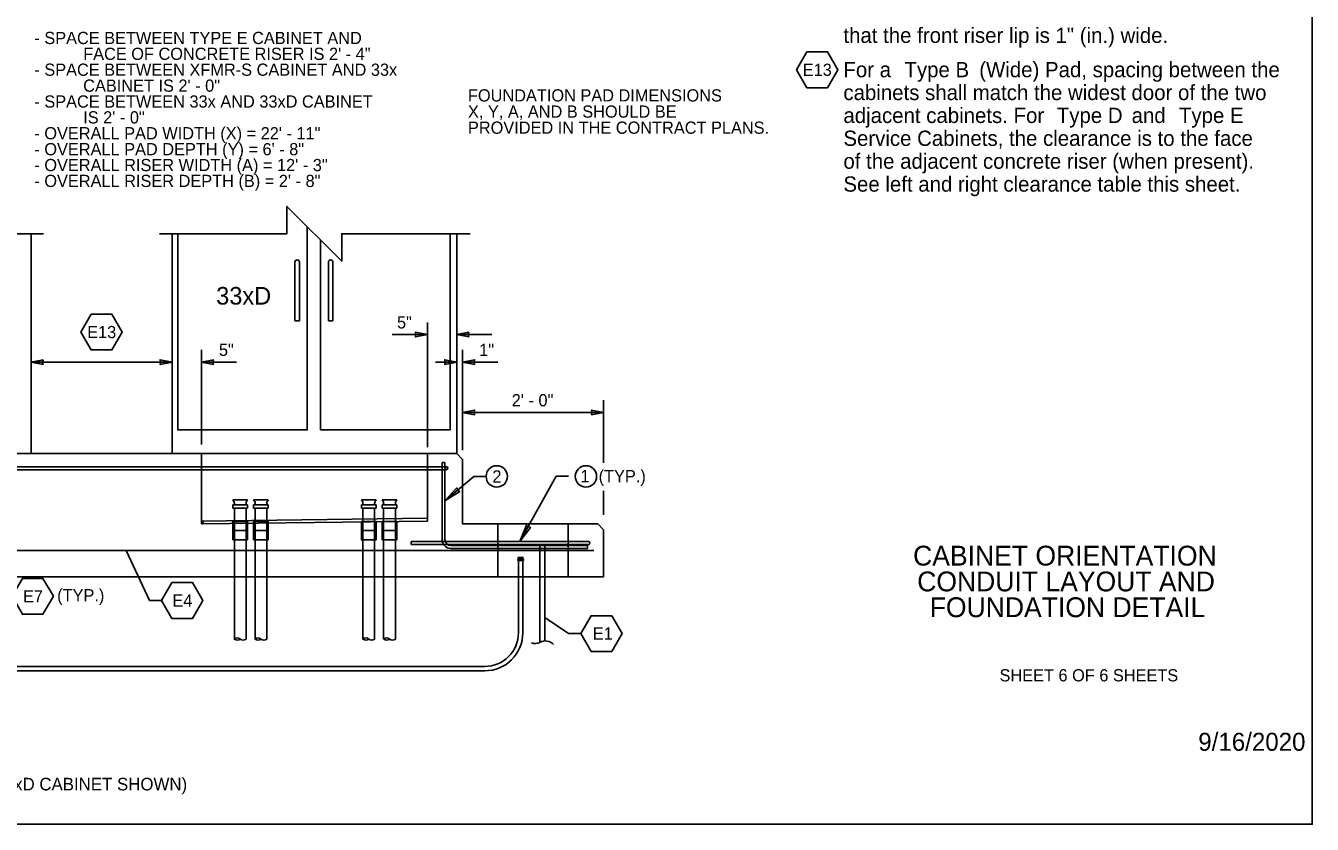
# Model space of a CAD drawing. Extents: x 99862 to 103151, y 100000 to 117076.
# Drawn here: x 101465 to 103151, y 115000 to 116046 of the extents above; entities that cross this region are included whole.
import ezdxf

# ---------------------------------------------------------------- set-up
doc = ezdxf.new("R2010")
doc.units = 0
for name, color, linetype in [('Default', 7, 'Continuous'), ('Level 1', 7, 'Continuous'), ('Level 11', 7, 'Continuous'), ('Level 15', 7, 'Continuous'), ('Level 20', 7, 'Continuous'), ('Level 40', 7, 'Continuous'), ('Level 6', 7, 'Continuous'), ('Level 62', 7, 'Continuous')]:
    doc.layers.add(name, color=color, linetype=linetype)

msp = doc.modelspace()

# ---------------------------------------------------------------- linework, layer by layer
at = {"layer": 'Default'}
for p, q in [((102010.5, 115372.6), (102010.5, 115473.9)), ((102010.5, 115473.9), (102014.3, 115473.9)), ((102014.3, 115372.6), (102014.3, 115473.9)), ((100931.3, 115468.2), (102016.3, 115468.2)), ((100931.3, 115464.3), (102016.3, 115464.3)), ((102202.3, 115370.1), (101969.8, 115370.1)), ((101969.8, 115370.1), (101969.8, 115366.3)), ((101969.8, 115370.1), (101969.8, 115366.3)), ((102202.3, 115366.3), (101969.8, 115366.3)), ((102200.9, 115364.9), (102022, 115364.9)), ((102200.9, 115361.1), (102022, 115361.1)), ((102200.9, 115364.9), (102200.9, 115361.1))]:
    msp.add_line(p, q, dxfattribs=at)
for centre, radius in [((102016.3, 115466.3), 1.92), ((101696.5, 115394.6), 1.44)]:
    msp.add_circle(centre, radius, dxfattribs=at)
for centre, radius, start, end in [((102022, 115372.6), 11.5, 180, 270), ((102022, 115372.6), 7.7, 180, 270), ((102202.3, 115368.2), 1.92, 270, 90)]:
    msp.add_arc(centre, radius, start, end, dxfattribs=at)
at = {"layer": 'Level 1'}
for p, q in [((101656.5, 115773.5), (101656.5, 115485.5)), ((102029.7, 115773.5), (102029.7, 115485.5)), ((101817.7, 115732.5), (101817.7, 115736.4)), ((101817.7, 115659.2), (101817.7, 115732.5)), ((101823.5, 115736.4), (101823.5, 115732.5)), ((101823.5, 115732.5), (101823.5, 115659.2)), ((101861.5, 115736.4), (101861.5, 115732.5)), ((101861.5, 115732.5), (101861.5, 115659.2)), ((101867.3, 115732.5), (101867.3, 115736.4)), ((101867.3, 115659.2), (101867.3, 115732.5)), ((101823.5, 115659.2), (101817.7, 115659.2)), ((101861.5, 115659.2), (101867.3, 115659.2)), ((101736.3, 115424.6), (101755.5, 115424.6)), ((101763.5, 115424.6), (101782.7, 115424.6)), ((101904.8, 115424.6), (101924, 115424.6)), ((101932, 115424.6), (101951.3, 115424.6)), ((101736.3, 115418.3), (101736.3, 115413.7)), ((101736.3, 115418.3), (101755.5, 115418.3)), ((101736.3, 115413.7), (101755.5, 115413.7)), ((101738.2, 115420.1), (101738.2, 115418.3)), ((101738.2, 115384.4), (101738.2, 115413.7)), ((101753.6, 115420.1), (101753.6, 115418.3)), ((101753.6, 115384.4), (101753.6, 115413.7)), ((101755.5, 115418.3), (101755.5, 115413.7)), ((101763.5, 115418.3), (101763.5, 115413.7)), ((101763.5, 115418.3), (101782.7, 115418.3)), ((101763.5, 115413.7), (101782.7, 115413.7)), ((101765.4, 115420.1), (101765.4, 115418.3)), ((101765.4, 115384.4), (101765.4, 115413.7)), ((101780.8, 115420.1), (101780.8, 115418.3)), ((101780.8, 115384.4), (101780.8, 115413.7)), ((101782.7, 115418.3), (101782.7, 115413.7)), ((101904.8, 115418.3), (101904.8, 115413.7)), ((101904.8, 115418.3), (101924, 115418.3)), ((101904.8, 115413.7), (101924, 115413.7)), ((101906.7, 115420.1), (101906.7, 115418.3)), ((101906.7, 115384.4), (101906.7, 115413.7)), ((101922.1, 115420.1), (101922.1, 115418.3)), ((101922.1, 115384.4), (101922.1, 115413.7)), ((101924, 115418.3), (101924, 115413.7)), ((101932, 115418.3), (101932, 115413.7)), ((101932, 115418.3), (101951.3, 115418.3)), ((101932, 115413.7), (101951.3, 115413.7)), ((101933.9, 115420.1), (101933.9, 115418.3)), ((101933.9, 115384.4), (101933.9, 115413.7)), ((101949.3, 115420.1), (101949.3, 115418.3)), ((101949.3, 115384.4), (101949.3, 115413.7)), ((101951.3, 115418.3), (101951.3, 115413.7)), ((101753.6, 115384.4), (101738.2, 115384.4)), ((101738.2, 115384.4), (101738.2, 115242.3)), ((101753.6, 115384.4), (101753.6, 115242.3)), ((101780.8, 115384.4), (101765.4, 115384.4)), ((101765.4, 115384.4), (101765.4, 115242.3)), ((101780.8, 115384.4), (101780.8, 115242.3)), ((101922.1, 115384.4), (101906.7, 115384.4)), ((101906.7, 115384.4), (101906.7, 115242.3)), ((101922.1, 115384.4), (101922.1, 115242.3)), ((101949.3, 115384.4), (101933.9, 115384.4)), ((101933.9, 115384.4), (101933.9, 115242.3)), ((101949.3, 115384.4), (101949.3, 115242.3)), ((102109.8, 115349.3), (102117, 115349.3)), ((102109.8, 115347), (102109.8, 115345.3)), ((102109.8, 115347), (102117, 115347)), ((102109.8, 115345.3), (102117, 115345.3)), ((102110.5, 115347.6), (102110.5, 115347)), ((102110.5, 115249), (102110.5, 115345.3)), ((102116.3, 115347.6), (102116.3, 115347)), ((102116.3, 115248.9), (102116.3, 115345.3)), ((102117, 115347), (102117, 115345.3)), ((100236.1, 115206.3), (102066.3, 115206.3)), ((100236.1, 115200.5), (102066.3, 115200.5))]:
    msp.add_line(p, q, dxfattribs=at)
for points in [[(99862, 114999.5), (103151, 114999.5), (103151, 117075.5), (99862, 117075.5)], [(101755.5, 115372.5), (101736.3, 115372.5), (101736.3, 115396.3), (101755.5, 115396.3)], [(101782.7, 115372.5), (101763.5, 115372.5), (101763.5, 115396.3), (101782.7, 115396.3)], [(101924, 115372.5), (101904.8, 115372.5), (101904.8, 115396.3), (101924, 115396.3)], [(101951.3, 115372.5), (101932, 115372.5), (101932, 115396.3), (101951.3, 115396.3)], [(102138.8, 115366.3), (102138.8, 115237.8), (102141, 115238.9), (102143, 115239.5), (102145.1, 115239.8), (102145.1, 115366.3)]]:
    msp.add_lwpolyline(points, close=True, dxfattribs=at)
for points in [[(101833.8, 115782.8), (101833.8, 115516.4), (101664, 115516.4), (101664, 115773.5)], [(102021, 115773.5), (102021, 115516.4), (101851.2, 115516.4), (101851.2, 115765.4)]]:
    msp.add_lwpolyline(points, dxfattribs=at)
for centre, radius, start, end in [((101820.6, 115736.4), 2.9, 0, 180), ((101864.4, 115736.4), 2.9, 0, 180), ((101731.9, 115420.1), 6.32, 0, 45.9402), ((101759.9, 115420.1), 6.32, 134.0598, 180), ((101759.1, 115420.1), 6.32, 0, 45.9402), ((101787.1, 115420.1), 6.32, 134.0598, 180), ((101900.4, 115420.1), 6.32, 0, 45.9402), ((101928.4, 115420.1), 6.32, 134.0598, 180), ((101927.6, 115420.1), 6.32, 0, 45.9402), ((101955.7, 115420.1), 6.32, 134.0598, 180), ((102108.1, 115347.6), 2.37, 0, 45.9402), ((102118.6, 115347.6), 2.37, 134.0598, 180), ((101742, 115237.6), 6.09, 50.8329, 129.1671), ((101742, 115247), 6.09, 230.8329, 309.1671), ((101749.7, 115247), 6.09, 230.8329, 309.1671), ((101769.2, 115237.6), 6.09, 50.8329, 129.1671), ((101769.2, 115247), 6.09, 230.8329, 309.1671), ((101776.9, 115247), 6.09, 230.8329, 309.1671), ((101910.6, 115237.6), 6.09, 50.8329, 129.1671), ((101910.6, 115247), 6.09, 230.8329, 309.1671), ((101918.3, 115247), 6.09, 230.8329, 309.1671), ((101937.8, 115237.6), 6.09, 50.8329, 129.1671), ((101937.8, 115247), 6.09, 230.8329, 309.1671), ((101945.5, 115247), 6.09, 230.8329, 309.1671), ((102066.3, 115250.6), 44.3, 270, 0), ((102066.3, 115250.6), 50, 270, 0), ((102132.5, 115251), 14.6, 250.7571, 295.3506), ((102146, 115225.7), 14.1, 42.3778, 121.1813)]:
    msp.add_arc(centre, radius, start, end, dxfattribs=at)
at = {"layer": 'Level 11'}
for p, q in [((101695, 115485.5), (101695, 115393.2)), ((101991.3, 115485.5), (101991.3, 115397)), ((101991.3, 115400.8), (101695, 115397)), ((101695, 115393.2), (101991.3, 115397)), ((102083.6, 115393.2), (102083.6, 115323.9)), ((102175.9, 115393.2), (102175.9, 115323.9))]:
    msp.add_line(p, q, dxfattribs=at)
for points in [[(100917.8, 115485.5), (102029.7, 115485.5)], [(102029.7, 115485.5), (102037.4, 115477.8), (102037.4, 115393.2)], [(102222.1, 115323.9), (102222.1, 115385.5), (102214.4, 115393.2), (102037.4, 115393.2)], [(100102.1, 115323.9), (102222.1, 115323.9)]]:
    msp.add_lwpolyline(points, dxfattribs=at)
at = {"layer": 'Level 15'}
for p, q in [((101991.2, 115641.4), (101945.1, 115641.4)), ((101991.2, 115493.9), (101991.2, 115657.4)), ((102029.7, 115641.4), (102075.9, 115641.4)), ((101695, 115497.5), (101695, 115621.3)), ((102037.4, 115489.8), (102037.4, 115621.3)), ((101471.8, 115605.3), (101656.5, 115605.3)), ((101695, 115605.3), (101741.2, 115605.3)), ((102029.7, 115605.3), (102001.7, 115605.3)), ((102037.4, 115605.3), (102083.6, 115605.3)), ((102222.1, 115473.1), (102222.1, 115555.3)), ((102222.1, 115539.3), (102037.4, 115539.3)), ((102112.5, 115370.1), (102160.2, 115455.9)), ((102176.3, 115455.9), (102160.3, 115455.9)), ((102014.3, 115423.3), (102052.2, 115455.4)), ((102068.2, 115455.4), (102052.2, 115455.4)), ((102222.1, 115436.4), (102222.1, 115405.2)), ((101596.5, 115358.5), (101626.8, 115292.8)), ((101642.8, 115292.8), (101626.8, 115292.8)), ((102145.1, 115270.4), (102176.2, 115249.5)), ((102192.2, 115249.5), (102176.2, 115249.5))]:
    msp.add_line(p, q, dxfattribs=at)
for points in [[(101488, 115773.5), (101415.4, 115773.5), (101415.4, 115737.6), (101343.6, 115809.4), (101343.6, 115773.5), (101261.1, 115773.5)], [(102047.2, 115773.5), (101879, 115773.5), (101879, 115737.6), (101807.2, 115809.4), (101807.2, 115773.5), (101640.2, 115773.5)]]:
    msp.add_lwpolyline(points, dxfattribs=at)
for points in [[(101991.2, 115641.4), (101975.5, 115638.3), (101976.2, 115641.4), (101975.5, 115644.5)], [(102029.7, 115641.4), (102045.5, 115638.3), (102044.7, 115641.4), (102045.5, 115644.5)], [(101471.8, 115605.3), (101487.6, 115602.2), (101486.8, 115605.3), (101487.6, 115608.3)], [(101656.5, 115605.3), (101640.8, 115602.2), (101641.5, 115605.3), (101640.8, 115608.3)], [(101695, 115605.3), (101710.7, 115602.2), (101710, 115605.3), (101710.7, 115608.3)], [(102029.7, 115605.3), (102014, 115602.2), (102014.7, 115605.3), (102014, 115608.3)], [(102037.4, 115605.3), (102053.1, 115602.2), (102052.4, 115605.3), (102053.1, 115608.3)], [(102037.4, 115539.3), (102053.1, 115536.2), (102052.4, 115539.3), (102053.1, 115542.4)], [(102222.1, 115539.3), (102206.4, 115536.2), (102207.1, 115539.3), (102206.4, 115542.4)], [(102014.3, 115423.3), (102029.8, 115440.3), (102031, 115437.4), (102033.7, 115435.8)], [(102112.5, 115370.1), (102126.2, 115388.6), (102123.1, 115389.2), (102121, 115391.6)]]:
    msp.add_lwpolyline(points, close=True, dxfattribs=at)
at = {"layer": 'Level 20'}
for points in [[(102475.1, 115988.5), (102488.6, 116011.9), (102515.6, 116011.9), (102529.2, 115988.5), (102515.6, 115965), (102488.6, 115965), (102475.1, 115988.5)], [(101537.1, 115644.7), (101550.6, 115668.1), (101577.7, 115668.1), (101591.2, 115644.7), (101577.7, 115621.3), (101550.6, 115621.3), (101537.1, 115644.7)], [(101446.9, 115298.3), (101460.4, 115321.8), (101487.4, 115321.8), (101501, 115298.3), (101487.4, 115274.9), (101460.4, 115274.9), (101446.9, 115298.3)], [(101642.8, 115292.8), (101656.3, 115316.2), (101683.4, 115316.2), (101696.9, 115292.8), (101683.4, 115269.4), (101656.3, 115269.4), (101642.8, 115292.8)], [(102192.2, 115249.5), (102205.7, 115272.9), (102232.8, 115272.9), (102246.3, 115249.5), (102232.8, 115226.1), (102205.7, 115226.1), (102192.2, 115249.5)]]:
    msp.add_lwpolyline(points, dxfattribs=at)
for centre in [(102082.2, 115455.4), (102199, 115455.4)]:
    msp.add_circle(centre, 14, dxfattribs=at)
at = {"layer": 'Level 40'}
msp.add_line((100115, 115358.5), (102209.3, 115358.5), dxfattribs=at)
at = {"layer": 'Level 6'}
msp.add_line((101471.8, 115773.5), (101471.8, 115485.5), dxfattribs=at)

# ---------------------------------------------------------------- texts
at = {"layer": 'Level 1'}
msp.add_text('33xD', height=23.09, dxfattribs=at).set_placement((101714.4, 115680.7))
at = {"layer": 'Level 15'}
msp.add_text('9/16/2020', height=23.62, dxfattribs=at).set_placement((103001.6, 115095.8))
at = {"layer": 'Level 20'}
for s, height, p in [('- SPACE BETWEEN TYPE E CABINET AND', 16, (101476.1, 116022.2)), ('that the front riser lip is 1" (in.) wide.', 20, (102536.5, 116023.7)), ('FACE OF CONCRETE RISER IS 2\' - 4"', 16, (101540.1, 116001.4)), ('- SPACE BETWEEN XFMR-S CABINET AND 33x', 16, (101476.1, 115980.6)), ('E13', 16, (102483.2, 115980.5)), ('For a ', 20, (102536.5, 115978.7)), ('Type B', 20, (102616.5, 115978.7)), (' (Wide) Pad, spacing between the', 20, (102707.1, 115978.7)), ('CABINET IS 2\' - 0"', 16, (101540.1, 115959.7)), ('FOUNDATION PAD DIMENSIONS', 16, (102044.4, 115946.9)), ('cabinets shall match the widest door of the two', 20, (102536.5, 115948.7)), ('- SPACE BETWEEN 33x AND 33xD CABINET', 16, (101476.1, 115938.9)), ('IS 2\' - 0"', 16, (101540.1, 115918.1)), ('X, Y, A, AND B SHOULD BE', 16, (102044.4, 115925.7)), ('adjacent cabinets. For ', 20, (102536.5, 115918.7)), ('Type D', 20, (102816.2, 115918.7)), (' and ', 20, (102906.8, 115918.7)), ('Type E', 20, (102976.3, 115918.7)), ('- OVERALL PAD WIDTH (X) = 22\' - 11"', 16, (101476.1, 115897.3)), ('PROVIDED IN THE CONTRACT PLANS.', 16, (102044.4, 115904.6)), ('Service Cabinets, the clearance is to the face', 20, (102536.5, 115888.7)), ('- OVERALL PAD DEPTH (Y) = 6\' - 8"', 16, (101476.1, 115876.4)), ('of the adjacent concrete riser (when present).', 20, (102536.5, 115858.7)), ('- OVERALL RISER WIDTH (A) = 12\' - 3"', 16, (101476.1, 115855.6)), ('- OVERALL RISER DEPTH (B) = 2\' - 8"', 16, (101476.1, 115834.8)), ('See left and right clearance table this sheet.', 20, (102536.5, 115828.7)), ('5"', 16, (101951.4, 115649.4)), ('E13', 16, (101545.3, 115636.7)), ('5"', 16, (101718, 115613.3)), ('1"', 16, (102059.1, 115613.3)), ('2\' - 0"', 16, (102101.8, 115547.3)), ('2', 16, (102076.4, 115447.4)), ('1  (TYP.)', 16, (102191.9, 115447.9)), ('E7', 16, (101461.2, 115290.3)), ('(TYP.)', 16, (101506, 115291.7)), ('E4', 16, (101657, 115284.8)), ('E1', 16, (102208, 115241.5)), ('(TYPE E SERVICE CABINET, XFMR-S CABINET, TYPE 33x CABINET, AND TYPE 33xD CABINET SHOWN)', 16.5, (100593.8, 115043.9))]:
    msp.add_text(s, height=height, dxfattribs=at).set_placement(p)
at = {"layer": 'Level 62'}
for s, height, p in [('CABINET ORIENTATION', 26, (102627.8, 115338.6)), ('CONDUIT LAYOUT AND', 26, (102633.2, 115304.8)), ('FOUNDATION DETAIL', 26, (102649.6, 115271)), ('SHEET 6 OF 6 SHEETS', 16, (102741.1, 115186.8))]:
    msp.add_text(s, height=height, dxfattribs=at).set_placement(p)

doc.saveas('drawing.dxf')
